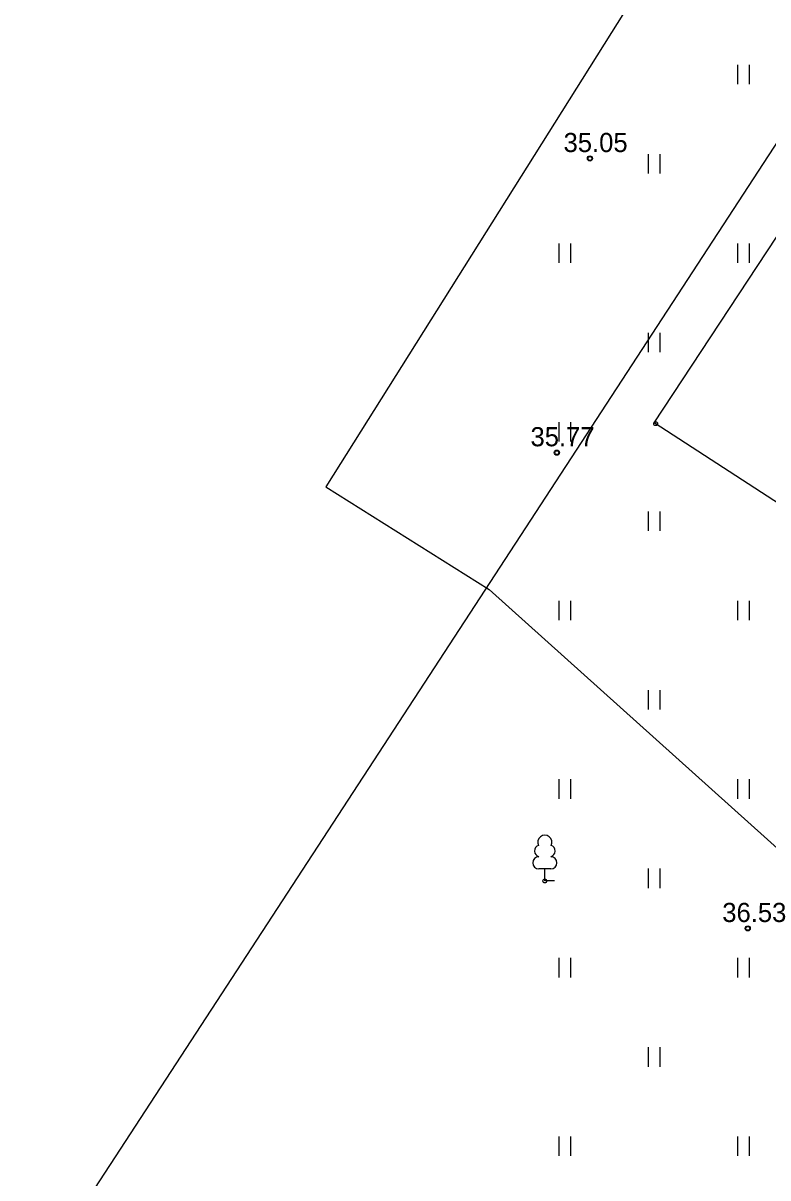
# Model space of a CAD drawing. Extents: x 641898 to 642452, y 6471715 to 6472255.
# Drawn here: x 641967.79 to 641996.97, y 6472135.67 to 6472180.93 of the extents above; entities that cross this region are included whole.
import ezdxf

# ---------------------------------------------------------------- set-up
doc = ezdxf.new("R2010")
doc.units = 0
for name, color, linetype in [('HALJASTUS', 7, 'Continuous'), ('HOONE', 7, 'Continuous'), ('KORGUS-EH2000', 7, 'Continuous'), ('MOOTMPUNKT', 7, 'Continuous'), ('MOOTPIIR', 7, 'Continuous'), ('PIIR', 7, 'Continuous'), ('PUU', 7, 'Continuous')]:
    doc.layers.add(name, color=color, linetype=linetype)

msp = doc.modelspace()

# ---------------------------------------------------------------- linework, layer by layer
at = {"layer": 'HALJASTUS'}
for p, q in [((641995.775, 6472179.295), (641995.775, 6472178.534)), ((641996.23, 6472179.295), (641996.23, 6472178.534)), ((641992.275, 6472175.795), (641992.275, 6472175.034)), ((641992.73, 6472175.795), (641992.73, 6472175.034)), ((641988.775, 6472172.295), (641988.775, 6472171.534)), ((641989.23, 6472172.295), (641989.23, 6472171.534)), ((641995.775, 6472172.295), (641995.775, 6472171.534)), ((641996.23, 6472172.295), (641996.23, 6472171.534)), ((641992.275, 6472168.795), (641992.275, 6472168.034)), ((641992.73, 6472168.795), (641992.73, 6472168.034)), ((641988.775, 6472165.295), (641988.775, 6472164.534)), ((641989.23, 6472165.295), (641989.23, 6472164.534)), ((641992.275, 6472161.795), (641992.275, 6472161.034)), ((641992.73, 6472161.795), (641992.73, 6472161.034)), ((641988.775, 6472158.295), (641988.775, 6472157.534)), ((641989.23, 6472158.295), (641989.23, 6472157.534)), ((641995.775, 6472158.295), (641995.775, 6472157.534)), ((641996.23, 6472158.295), (641996.23, 6472157.534)), ((641992.275, 6472154.795), (641992.275, 6472154.034)), ((641992.73, 6472154.795), (641992.73, 6472154.034)), ((641988.775, 6472151.295), (641988.775, 6472150.534)), ((641989.23, 6472151.295), (641989.23, 6472150.534)), ((641995.775, 6472151.295), (641995.775, 6472150.534)), ((641996.23, 6472151.295), (641996.23, 6472150.534)), ((641992.275, 6472147.795), (641992.275, 6472147.034)), ((641992.73, 6472147.795), (641992.73, 6472147.034)), ((641988.775, 6472144.295), (641988.775, 6472143.534)), ((641989.23, 6472144.295), (641989.23, 6472143.534)), ((641995.775, 6472144.295), (641995.775, 6472143.534)), ((641996.23, 6472144.295), (641996.23, 6472143.534)), ((641992.275, 6472140.795), (641992.275, 6472140.034)), ((641992.73, 6472140.795), (641992.73, 6472140.034)), ((641988.775, 6472137.295), (641988.775, 6472136.534)), ((641989.23, 6472137.295), (641989.23, 6472136.534)), ((641995.775, 6472137.295), (641995.775, 6472136.534)), ((641996.23, 6472137.295), (641996.23, 6472136.534))]:
    msp.add_line(p, q, dxfattribs=at)
at = {"layer": 'HOONE'}
msp.add_lwpolyline([(641999.152, 6472175.34), (642018.08, 6472163.129), (642011.231, 6472153.121), (641992.517, 6472165.267), (641999.152, 6472175.34)], dxfattribs=at)
at = {"layer": 'KORGUS-EH2000'}
for centre in [(641989.998, 6472175.627), (641988.702, 6472164.097), (641996.181, 6472145.453)]:
    msp.add_circle(centre, 0.1, dxfattribs=at)
at = {"layer": 'MOOTMPUNKT'}
for centre in [(641989.998, 6472175.627), (641992.573, 6472165.231), (641988.702, 6472164.097), (641988.23, 6472147.311), (641996.181, 6472145.453)]:
    msp.add_circle(centre, 0.075, dxfattribs=at)
at = {"layer": 'MOOTPIIR'}
msp.add_lwpolyline([(642014.306, 6472085.384), (642027.67, 6472104.979), (642055.501, 6472084.843), (642081.563, 6472094.262), (642123.938, 6472142.273), (642065.721, 6472244.475), (642008.922, 6472196.948), (642003.347, 6472200.453), (641979.65, 6472162.756), (641979.65, 6472162.756), (641986.045, 6472158.736), (642004.269, 6472142.365), (641987.048, 6472123.488), (641970.482, 6472097.889), (641986.758, 6472084.396)], close=True, dxfattribs=at)
at = {"layer": 'PIIR'}
msp.add_line((642000.12, 6472180.55), (641967.79, 6472130.98), dxfattribs=at)
at = {"layer": 'PUU'}
for p, q in [((641988.47, 6472147.786), (641987.99, 6472147.786)), ((641988.23, 6472147.311), (641988.23, 6472147.786)), ((641988.61, 6472147.311), (641988.23, 6472147.311))]:
    msp.add_line(p, q, dxfattribs=at)
for centre, radius, start, end in [((641988.23, 6472148.831), 0.277, 332.5799, 207.4201), ((641988.06, 6472148.484), 0.233, 109.0217, 253.1415), ((641988.4, 6472148.484), 0.233, 286.8508, 70.9859), ((641987.993, 6472148.023), 0.238, 90.0016, 269.3953), ((641988.467, 6472148.023), 0.238, 270.6047, 89.9984)]:
    msp.add_arc(centre, radius, start, end, dxfattribs=at)

# ---------------------------------------------------------------- texts
at = {"layer": 'KORGUS-EH2000'}
for s, p in [('35.05', (641988.965, 6472175.877)), ('35.77', (641987.669, 6472164.347)), ('36.53', (641995.183, 6472145.703))]:
    msp.add_text(s, height=0.75, dxfattribs=at).set_placement(p)

doc.saveas('drawing.dxf')
